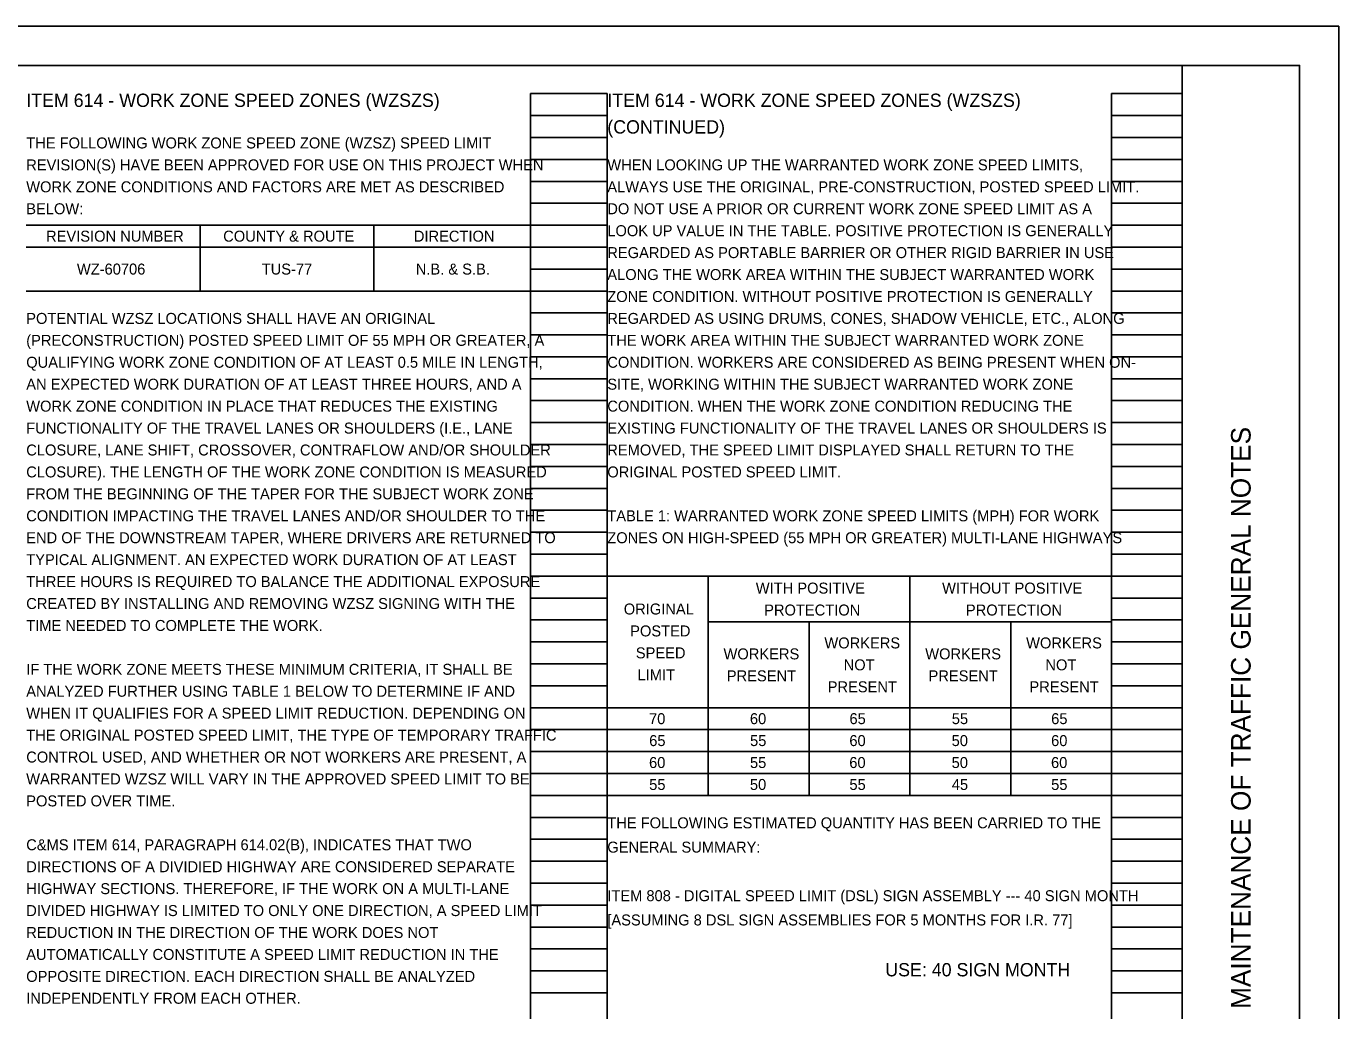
# Model space of a CAD drawing. Extents: x 0 to 34, y 0 to 22.
# Drawn here: x 17.24 to 34, y 9.43 to 22 of the extents above; entities that cross this region are included whole.
import ezdxf

# ---------------------------------------------------------------- set-up
doc = ezdxf.new("R2010")
doc.units = 0
for name, color, linetype in [('SH_Border', 7, 'Continuous'), ('SH_Cut_Line', 7, 'Continuous'), ('SH_Data', 7, 'Continuous'), ('SH_Text', 7, 'Continuous')]:
    doc.layers.add(name, color=color, linetype=linetype)

msp = doc.modelspace()

# ---------------------------------------------------------------- linework, layer by layer
at = {"layer": 'SH_Border'}
msp.add_line((32, 0.5), (32, 21.5), dxfattribs=at)
msp.add_lwpolyline([(1.5, 21.5), (33.5, 21.5), (33.5, 0.5), (1.5, 0.5)], close=True, dxfattribs=at)
at = {"layer": 'SH_Cut_Line'}
msp.add_lwpolyline([(0, 0), (34, 0), (34, 22), (0, 22)], close=True, dxfattribs=at)
at = {"layer": 'SH_Data'}
for p, q in [((23.68, 0.98), (23.68, 21.14)), ((23.68, 21.14), (24.66, 21.14)), ((24.66, 0.98), (24.66, 21.14)), ((31.1, 0.98), (31.1, 21.14)), ((31.1, 21.14), (32, 21.14)), ((32, 0.98), (32, 21.14)), ((23.68, 20.86), (24.66, 20.86)), ((31.1, 20.86), (32, 20.86)), ((23.68, 20.58), (24.66, 20.58)), ((31.1, 20.58), (32, 20.58)), ((23.68, 20.3), (24.66, 20.3)), ((31.1, 20.3), (32, 20.3)), ((23.68, 20.02), (24.66, 20.02)), ((31.1, 20.02), (32, 20.02)), ((23.68, 19.74), (24.66, 19.74)), ((31.1, 19.74), (32, 19.74)), ((19.46, 19.46), (19.46, 18.62)), ((21.68, 19.46), (21.68, 18.62)), ((23.68, 19.46), (24.66, 19.46)), ((31.1, 19.46), (32, 19.46)), ((23.68, 19.18), (24.66, 19.18)), ((31.1, 19.18), (32, 19.18)), ((23.68, 18.9), (24.66, 18.9)), ((31.1, 18.9), (32, 18.9)), ((23.68, 18.62), (24.66, 18.62)), ((31.1, 18.62), (32, 18.62)), ((23.68, 18.34), (24.66, 18.34)), ((31.1, 18.34), (32, 18.34)), ((23.68, 18.06), (24.66, 18.06)), ((31.1, 18.06), (32, 18.06)), ((23.68, 17.78), (24.66, 17.78)), ((31.1, 17.78), (32, 17.78)), ((23.68, 17.5), (24.66, 17.5)), ((31.1, 17.5), (32, 17.5)), ((23.68, 17.22), (24.66, 17.22)), ((31.1, 17.22), (32, 17.22)), ((23.68, 16.94), (24.66, 16.94)), ((31.1, 16.94), (32, 16.94)), ((23.68, 16.66), (24.66, 16.66)), ((31.1, 16.66), (32, 16.66)), ((23.68, 16.38), (24.66, 16.38)), ((31.1, 16.38), (32, 16.38)), ((23.68, 16.1), (24.66, 16.1)), ((31.1, 16.1), (32, 16.1)), ((23.68, 15.82), (24.66, 15.82)), ((31.1, 15.82), (32, 15.82)), ((23.68, 15.54), (24.66, 15.54)), ((31.1, 15.54), (32, 15.54)), ((23.68, 15.26), (24.66, 15.26)), ((31.1, 15.26), (32, 15.26)), ((23.68, 14.98), (24.66, 14.98)), ((24.66, 14.98), (31.1, 14.98)), ((24.66, 14.98), (24.66, 12.18)), ((25.948, 14.98), (25.948, 12.18)), ((28.524, 14.98), (28.524, 12.18)), ((31.1, 14.98), (32, 14.98)), ((31.1, 14.98), (31.1, 12.18)), ((23.68, 14.7), (24.66, 14.7)), ((31.1, 14.7), (32, 14.7)), ((23.68, 14.42), (24.66, 14.42)), ((31.1, 14.42), (32, 14.42)), ((25.948, 14.395), (31.1, 14.395)), ((27.236, 14.395), (27.236, 12.18)), ((29.812, 14.395), (29.812, 12.18)), ((23.68, 14.14), (24.66, 14.14)), ((31.1, 14.14), (32, 14.14)), ((23.68, 13.86), (24.66, 13.86)), ((31.1, 13.86), (32, 13.86)), ((23.68, 13.58), (24.66, 13.58)), ((31.1, 13.58), (32, 13.58)), ((23.68, 13.3), (24.66, 13.3)), ((24.66, 13.3), (31.1, 13.3)), ((31.1, 13.3), (32, 13.3)), ((23.68, 13.02), (24.66, 13.02)), ((24.66, 13.02), (31.1, 13.02)), ((31.1, 13.02), (32, 13.02)), ((23.68, 12.74), (24.66, 12.74)), ((24.66, 12.74), (31.1, 12.74)), ((31.1, 12.74), (32, 12.74)), ((23.68, 12.46), (24.66, 12.46)), ((24.66, 12.46), (31.1, 12.46)), ((31.1, 12.46), (32, 12.46)), ((23.68, 12.18), (24.66, 12.18)), ((24.66, 12.18), (31.1, 12.18)), ((31.1, 12.18), (32, 12.18)), ((23.68, 11.9), (24.66, 11.9)), ((31.1, 11.9), (32, 11.9)), ((23.68, 11.62), (24.66, 11.62)), ((31.1, 11.62), (32, 11.62)), ((23.68, 11.34), (24.66, 11.34)), ((31.1, 11.34), (32, 11.34)), ((23.68, 11.06), (24.66, 11.06)), ((31.1, 11.06), (32, 11.06)), ((23.68, 10.78), (24.66, 10.78)), ((31.1, 10.78), (32, 10.78)), ((23.68, 10.5), (24.66, 10.5)), ((31.1, 10.5), (32, 10.5)), ((23.68, 10.22), (24.66, 10.22)), ((31.1, 10.22), (32, 10.22)), ((23.68, 9.94), (24.66, 9.94)), ((31.1, 9.94), (32, 9.94)), ((23.68, 9.66), (24.66, 9.66)), ((31.1, 9.66), (32, 9.66))]:
    msp.add_line(p, q, dxfattribs=at)
at = {"layer": 'SH_Text'}
for p, q in [((17.24, 19.46), (23.68, 19.46)), ((23.68, 19.46), (23.68, 18.62)), ((17.24, 19.18), (23.68, 19.18)), ((17.24, 18.62), (23.68, 18.62))]:
    msp.add_line(p, q, dxfattribs=at)

# ---------------------------------------------------------------- texts
at = {"layer": 'SH_Data'}
msp.add_text('MAINTENANCE OF TRAFFIC GENERAL NOTES', height=0.25, rotation=90, dxfattribs=at).set_placement((32.875, 9.455))
at = {"layer": 'SH_Text'}
for s, height, p in [('ITEM 614 - WORK ZONE SPEED ZONES (WZSZS)', 0.17, (17.24, 20.97)), ('ITEM 614 - WORK ZONE SPEED ZONES (WZSZS)', 0.17, (24.66, 20.97)), ('(CONTINUED)', 0.17, (24.66, 20.63)), ('THE FOLLOWING WORK ZONE SPEED ZONE (WZSZ) SPEED LIMIT ', 0.14, (17.24, 20.44)), ('REVISION(S) HAVE BEEN APPROVED FOR USE ON THIS PROJECT WHEN ', 0.14, (17.24, 20.16)), ('WHEN LOOKING UP THE WARRANTED WORK ZONE SPEED LIMITS, ', 0.14, (24.66, 20.16)), ('WORK ZONE CONDITIONS AND FACTORS ARE MET AS DESCRIBED ', 0.14, (17.24, 19.88)), ('ALWAYS USE THE ORIGINAL, PRE-CONSTRUCTION, POSTED SPEED LIMIT. ', 0.14, (24.66, 19.88)), ('BELOW: ', 0.14, (17.24, 19.6)), ('DO NOT USE A PRIOR OR CURRENT WORK ZONE SPEED LIMIT AS A ', 0.14, (24.66, 19.6)), ('LOOK UP VALUE IN THE TABLE. POSITIVE PROTECTION IS GENERALLY ', 0.14, (24.66, 19.32)), ('REVISION NUMBER', 0.14, (17.493, 19.25)), ('COUNTY & ROUTE', 0.14, (19.755, 19.25)), ('DIRECTION', 0.14, (22.19, 19.25)), ('REGARDED AS PORTABLE BARRIER OR OTHER RIGID BARRIER IN USE ', 0.14, (24.66, 19.04)), ('WZ-60706', 0.14, (17.887, 18.83)), ('TUS-77', 0.14, (20.247, 18.83)), ('N.B. & S.B.', 0.14, (22.214, 18.83)), ('ALONG THE WORK AREA WITHIN THE SUBJECT WARRANTED WORK ', 0.14, (24.66, 18.76)), ('ZONE CONDITION. WITHOUT POSITIVE PROTECTION IS GENERALLY ', 0.14, (24.66, 18.48)), ('POTENTIAL WZSZ LOCATIONS SHALL HAVE AN ORIGINAL ', 0.14, (17.24, 18.2)), ('REGARDED AS USING DRUMS, CONES, SHADOW VEHICLE, ETC., ALONG ', 0.14, (24.66, 18.2)), ('(PRECONSTRUCTION) POSTED SPEED LIMIT OF 55 MPH OR GREATER, A ', 0.14, (17.24, 17.92)), ('THE WORK AREA WITHIN THE SUBJECT WARRANTED WORK ZONE ', 0.14, (24.66, 17.92)), ('QUALIFYING WORK ZONE CONDITION OF AT LEAST 0.5 MILE IN LENGTH, ', 0.14, (17.24, 17.64)), ('CONDITION. WORKERS ARE CONSIDERED AS BEING PRESENT WHEN ON-', 0.14, (24.66, 17.64)), ('AN EXPECTED WORK DURATION OF AT LEAST THREE HOURS, AND A ', 0.14, (17.24, 17.36)), ('SITE, WORKING WITHIN THE SUBJECT WARRANTED WORK ZONE ', 0.14, (24.66, 17.36)), ('WORK ZONE CONDITION IN PLACE THAT REDUCES THE EXISTING ', 0.14, (17.24, 17.08)), ('CONDITION. WHEN THE WORK ZONE CONDITION REDUCING THE ', 0.14, (24.66, 17.08)), ('FUNCTIONALITY OF THE TRAVEL LANES OR SHOULDERS (I.E., LANE ', 0.14, (17.24, 16.8)), ('EXISTING FUNCTIONALITY OF THE TRAVEL LANES OR SHOULDERS IS  ', 0.14, (24.66, 16.8)), ('CLOSURE, LANE SHIFT, CROSSOVER, CONTRAFLOW AND/OR SHOULDER ', 0.14, (17.24, 16.52)), ('REMOVED, THE SPEED LIMIT DISPLAYED SHALL RETURN TO THE ', 0.14, (24.66, 16.52)), ('CLOSURE). THE LENGTH OF THE WORK ZONE CONDITION IS MEASURED ', 0.14, (17.24, 16.24)), ('ORIGINAL POSTED SPEED LIMIT. ', 0.14, (24.66, 16.24)), ('FROM THE BEGINNING OF THE TAPER FOR THE SUBJECT WORK ZONE ', 0.14, (17.24, 15.96)), ('CONDITION IMPACTING THE TRAVEL LANES AND/OR SHOULDER TO THE ', 0.14, (17.24, 15.68)), ('TABLE 1: WARRANTED WORK ZONE SPEED LIMITS (MPH) FOR WORK ', 0.14, (24.66, 15.68)), ('END OF THE DOWNSTREAM TAPER, WHERE DRIVERS ARE RETURNED TO ', 0.14, (17.24, 15.4)), ('ZONES ON HIGH-SPEED (55 MPH OR GREATER) MULTI-LANE HIGHWAYS', 0.14, (24.66, 15.4)), ('TYPICAL ALIGNMENT. AN EXPECTED WORK DURATION OF AT LEAST ', 0.14, (17.24, 15.12)), ('THREE HOURS IS REQUIRED TO BALANCE THE ADDITIONAL EXPOSURE ', 0.14, (17.24, 14.84)), ('WITH POSITIVE ', 0.14, (26.556, 14.757)), ('WITHOUT POSITIVE ', 0.14, (28.935, 14.757)), ('CREATED BY INSTALLING AND REMOVING WZSZ SIGNING WITH THE ', 0.14, (17.24, 14.56)), ('ORIGINAL ', 0.14, (24.87, 14.49)), ('PROTECTION', 0.14, (26.663, 14.477)), ('PROTECTION', 0.14, (29.239, 14.477)), ('TIME NEEDED TO COMPLETE THE WORK.', 0.14, (17.24, 14.28)), ('POSTED', 0.14, (24.952, 14.21)), ('WORKERS', 0.14, (27.432, 14.057)), ('WORKERS', 0.14, (30.008, 14.057)), ('SPEED', 0.14, (25.024, 13.93)), ('WORKERS', 0.14, (26.144, 13.917)), ('NOT', 0.14, (27.678, 13.777)), ('WORKERS', 0.14, (28.72, 13.917)), ('NOT', 0.14, (30.254, 13.777)), ('IF THE WORK ZONE MEETS THESE MINIMUM CRITERIA, IT SHALL BE ', 0.14, (17.24, 13.72)), ('LIMIT', 0.14, (25.046, 13.65)), ('PRESENT', 0.14, (26.186, 13.637)), ('PRESENT', 0.14, (28.762, 13.637)), ('ANALYZED FURTHER USING TABLE 1 BELOW TO DETERMINE IF AND ', 0.14, (17.24, 13.44)), ('PRESENT', 0.14, (27.474, 13.497)), ('PRESENT', 0.14, (30.05, 13.497)), ('WHEN IT QUALIFIES FOR A SPEED LIMIT REDUCTION. DEPENDING ON ', 0.14, (17.24, 13.16)), ('70', 0.14, (25.193, 13.09)), ('60', 0.14, (26.481, 13.09)), ('65', 0.14, (27.752, 13.09)), ('55', 0.14, (29.059, 13.09)), ('65', 0.14, (30.328, 13.09)), ('THE ORIGINAL POSTED SPEED LIMIT, THE TYPE OF TEMPORARY TRAFFIC ', 0.14, (17.24, 12.88)), ('65', 0.14, (25.195, 12.81)), ('55', 0.14, (26.483, 12.81)), ('60', 0.14, (27.751, 12.81)), ('50', 0.14, (29.057, 12.81)), ('60', 0.14, (30.327, 12.81)), ('CONTROL USED, AND WHETHER OR NOT WORKERS ARE PRESENT, A ', 0.14, (17.24, 12.6)), ('60', 0.14, (25.193, 12.53)), ('55', 0.14, (26.482, 12.53)), ('60', 0.14, (27.75, 12.53)), ('50', 0.14, (29.057, 12.53)), ('60', 0.14, (30.326, 12.53)), ('WARRANTED WZSZ WILL VARY IN THE APPROVED SPEED LIMIT TO BE ', 0.14, (17.24, 12.32)), ('55', 0.14, (25.195, 12.25)), ('50', 0.14, (26.481, 12.25)), ('55', 0.14, (27.752, 12.25)), ('45', 0.14, (29.059, 12.25)), ('55', 0.14, (30.328, 12.25)), ('POSTED OVER TIME. ', 0.14, (17.24, 12.04)), ('THE FOLLOWING ESTIMATED QUANTITY HAS BEEN CARRIED TO THE ', 0.14, (24.66, 11.76)), ('C&MS ITEM 614, PARAGRAPH 614.02(B), INDICATES THAT TWO ', 0.14, (17.24, 11.48)), ('GENERAL SUMMARY:', 0.14, (24.66, 11.45)), ('DIRECTIONS OF A DIVIDIED HIGHWAY ARE CONSIDERED SEPARATE ', 0.14, (17.24, 11.2)), ('HIGHWAY SECTIONS. THEREFORE, IF THE WORK ON A MULTI-LANE ', 0.14, (17.24, 10.92)), ('ITEM 808 - DIGITAL SPEED LIMIT (DSL) SIGN ASSEMBLY --- 40 SIGN MONTH', 0.14, (24.66, 10.83)), ('DIVIDED HIGHWAY IS LIMITED TO ONLY ONE DIRECTION, A SPEED LIMIT ', 0.14, (17.24, 10.64)), ('[ASSUMING 8 DSL SIGN ASSEMBLIES FOR 5 MONTHS FOR I.R. 77]', 0.14, (24.66, 10.52)), ('REDUCTION IN THE DIRECTION OF THE WORK DOES NOT ', 0.14, (17.24, 10.36)), ('AUTOMATICALLY CONSTITUTE A SPEED LIMIT REDUCTION IN THE ', 0.14, (17.24, 10.08)), ('OPPOSITE DIRECTION. EACH DIRECTION SHALL BE ANALYZED ', 0.14, (17.24, 9.8)), ('   USE: 40 SIGN MONTH', 0.17, (28.02, 9.87)), ('INDEPENDENTLY FROM EACH OTHER. ', 0.14, (17.24, 9.52))]:
    msp.add_text(s, height=height, dxfattribs=at).set_placement(p)

doc.saveas('drawing.dxf')
